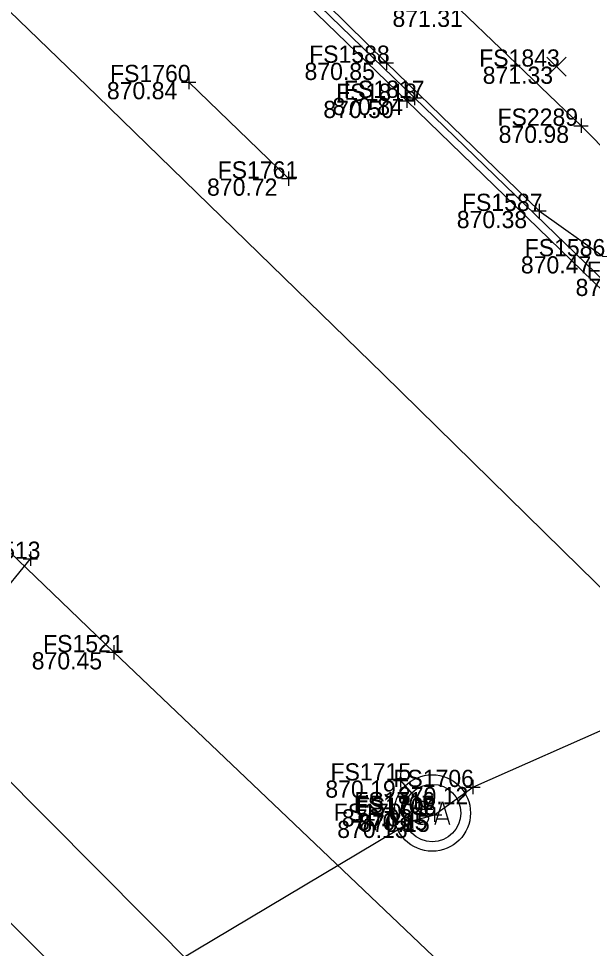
# Model space of a CAD drawing. Extents: x 1479420 to 1479833, y 379731 to 380103.
# Drawn here: x 1479593 to 1479633, y 379912.2 to 379977 of the extents above; entities that cross this region are included whole.
import ezdxf

# ---------------------------------------------------------------- set-up
doc = ezdxf.new("R2010")
doc.units = 0
for name, color, linetype in [('GK_Drainage_Nodes', 7, 'Continuous'), ('PM_X_CL_Double_Solid', 7, 'Continuous'), ('PM_X_Crosswalk', 7, 'Continuous'), ('PM_X_Lane_Line', 7, 'Continuous'), ('PV_X_Curb', 7, 'Continuous'), ('SV_X_Random_Point', 7, 'Continuous'), ('SV_X_Shot_Marker', 7, 'Continuous'), ('SV_X_Text_Elevation', 7, 'Continuous'), ('SV_X_Text_Name', 7, 'Continuous'), ('UT_X_Gas', 7, 'Continuous'), ('UT_X_Sanitary_Cells', 7, 'Continuous'), ('UT_X_Sanitary_Line', 7, 'Continuous'), ('UT_X_Water', 7, 'Continuous')]:
    doc.layers.add(name, color=color, linetype=linetype)

msp = doc.modelspace()

# ---------------------------------------------------------------- linework, layer by layer
at = {"layer": 'GK_Drainage_Nodes'}
for p, q in [((1479621.804, 379923.603), (1479621.804, 379923.603)), ((1479621.804, 379921.603), (1479621.804, 379921.603)), ((1479621.804, 379921.603), (1479621.804, 379921.603)), ((1479621.804, 379921.603), (1479621.804, 379921.603)), ((1479621.804, 379919.603), (1479621.804, 379919.603))]:
    msp.add_line(p, q, dxfattribs=at)
msp.add_circle((1479621.804, 379921.603), 2, dxfattribs=at)
at = {"layer": 'PM_X_CL_Double_Solid'}
msp.add_lwpolyline([(1479649.77, 379921.473), (1479632.094, 379938.759), (1479618.381, 379952.22), (1479598.438, 379971.627), (1479578.627, 379990.753), (1479560.467, 380008.345), (1479543.803, 380024.417)], dxfattribs=at)
at = {"layer": 'PM_X_Crosswalk'}
for p, q in [((1479636.371, 379879.555), (1479574.01, 379942.241)), ((1479627.792, 379878.685), (1479575.124, 379931.128))]:
    msp.add_line(p, q, dxfattribs=at)
at = {"layer": 'PM_X_Lane_Line'}
msp.add_line((1479604.82, 379972.583), (1479611.787, 379965.855), dxfattribs=at)
at = {"layer": 'PV_X_Curb'}
for points in [[(1479791.848, 380002.989), (1479773.254, 379993.873), (1479762.766, 379988.772), (1479738.122, 379976.643), (1479720.845, 379968.214), (1479698.694, 379957.239), (1479678.815, 379947.539), (1479674.951, 379945.56), (1479671.194, 379943.855), (1479668.836, 379942.929), (1479666.481, 379942.243), (1479664.295, 379941.704), (1479662.026, 379941.397), (1479659.994, 379941.512), (1479654.023, 379942.767), (1479648.758, 379945.101), (1479643.81, 379948.553), (1479642.638, 379949.516), (1479640.65, 379951.389), (1479638.379, 379953.495), (1479620.029, 379971.274), (1479601.931, 379988.801), (1479602.178, 379989.373), (1479582.142, 380008.015)], [(1479791.59, 380003.464), (1479772.982, 379994.381), (1479762.438, 379989.23), (1479737.891, 379977.225), (1479720.638, 379968.611), (1479698.71, 379957.883), (1479678.409, 379947.915), (1479674.816, 379946.157), (1479670.835, 379944.353), (1479668.74, 379943.532), (1479666.343, 379942.649), (1479664.179, 379942.195), (1479661.876, 379941.9), (1479659.999, 379941.971), (1479653.935, 379943.268), (1479649.182, 379945.527), (1479644.261, 379948.889), (1479643.432, 379949.993), (1479639.011, 379953.958), (1479638.818, 379953.848), (1479620.557, 379971.482), (1479582.44, 380008.391)]]:
    msp.add_lwpolyline(points, dxfattribs=at)
at = {"layer": 'SV_X_Random_Point'}
for p, q in [((1479629.807, 379972.993), (1479631.141, 379974.328)), ((1479629.807, 379974.328), (1479631.141, 379972.993))]:
    msp.add_line(p, q, dxfattribs=at)
at = {"layer": 'SV_X_Shot_Marker'}
for p, q in [((1479618.613, 379974.426), (1479618.613, 379973.426)), ((1479618.113, 379973.926), (1479619.113, 379973.926)), ((1479618.613, 379973.926), (1479618.613, 379973.926)), ((1479604.82, 379973.083), (1479604.82, 379972.083)), ((1479604.32, 379972.583), (1479605.32, 379972.583)), ((1479604.82, 379972.583), (1479604.82, 379972.583)), ((1479620.029, 379971.774), (1479620.029, 379970.774)), ((1479620.557, 379971.982), (1479620.557, 379970.982)), ((1479619.529, 379971.274), (1479620.529, 379971.274)), ((1479620.029, 379971.274), (1479620.029, 379971.274)), ((1479620.057, 379971.482), (1479621.057, 379971.482)), ((1479620.557, 379971.482), (1479620.557, 379971.482)), ((1479632.184, 379970.038), (1479632.184, 379969.038)), ((1479631.684, 379969.538), (1479632.684, 379969.538)), ((1479632.184, 379969.538), (1479632.184, 379969.538)), ((1479611.287, 379965.855), (1479612.287, 379965.855)), ((1479611.787, 379966.355), (1479611.787, 379965.355)), ((1479611.787, 379965.855), (1479611.787, 379965.855)), ((1479629.263, 379964.094), (1479629.263, 379963.094)), ((1479628.763, 379963.594), (1479629.763, 379963.594)), ((1479629.263, 379963.594), (1479629.263, 379963.594)), ((1479593.275, 379939.334), (1479594.275, 379939.334)), ((1479593.775, 379939.834), (1479593.775, 379938.834)), ((1479593.775, 379939.334), (1479593.775, 379939.334)), ((1479599.097, 379932.819), (1479600.097, 379932.819)), ((1479599.597, 379933.319), (1479599.597, 379932.319)), ((1479599.597, 379932.819), (1479599.597, 379932.819)), ((1479619.603, 379924.374), (1479619.603, 379923.374)), ((1479619.103, 379923.874), (1479620.103, 379923.874)), ((1479619.603, 379923.874), (1479619.603, 379923.874)), ((1479624.647, 379923.917), (1479624.647, 379922.917)), ((1479624.147, 379923.417), (1479625.147, 379923.417)), ((1479624.647, 379923.417), (1479624.647, 379923.417)), ((1479621.341, 379922.366), (1479621.341, 379921.366)), ((1479620.841, 379921.866), (1479621.841, 379921.866)), ((1479621.341, 379921.866), (1479621.341, 379921.866)), ((1479621.963, 379921.985), (1479621.963, 379920.985)), ((1479620.421, 379921.563), (1479620.421, 379920.563)), ((1479621.463, 379921.485), (1479622.463, 379921.485)), ((1479621.963, 379921.485), (1479621.963, 379921.485)), ((1479619.921, 379921.063), (1479620.921, 379921.063)), ((1479620.421, 379921.063), (1479620.421, 379921.063))]:
    msp.add_line(p, q, dxfattribs=at)
at = {"layer": 'UT_X_Gas'}
msp.add_lwpolyline([(1479590.076, 380006.869), (1479598.835, 379999.983), (1479606.591, 379993.985), (1479615.604, 379985.249), (1479623.747, 379977.629), (1479632.184, 379969.538), (1479638.836, 379962.809), (1479646.785, 379955.438), (1479652.981, 379949.433), (1479657.465, 379945.964), (1479660.591, 379945.024), (1479670.935, 379949.08), (1479679.157, 379953.065), (1479685.442, 379955.742), (1479689.462, 379958.127), (1479696.956, 379963.013), (1479705.088, 379967.488), (1479713.465, 379971.226), (1479723.024, 379975.676), (1479732.065, 379980.116), (1479742.535, 379985.018)], dxfattribs=at)
at = {"layer": 'UT_X_Sanitary_Cells'}
for points in [[(1479621.471, 379922.29), (1479621.446, 379922.315), (1479621.408, 379922.34), (1479621.295, 379922.378), (1479621.156, 379922.403), (1479621.056, 379922.403), (1479621.018, 379922.403), (1479620.854, 379922.365), (1479620.716, 379922.29), (1479620.627, 379922.189), (1479620.602, 379922.088), (1479620.602, 379922.013), (1479620.627, 379921.912), (1479620.728, 379921.824), (1479621.421, 379921.446), (1479621.484, 379921.396), (1479621.509, 379921.345), (1479621.534, 379921.27), (1479621.534, 379921.194), (1479621.522, 379921.118), (1479621.509, 379921.068), (1479621.484, 379921.005), (1479621.459, 379920.954), (1479621.434, 379920.917), (1479621.396, 379920.879), (1479621.358, 379920.854), (1479621.308, 379920.829), (1479621.27, 379920.816), (1479621.156, 379920.803), (1479620.98, 379920.803), (1479620.867, 379920.829), (1479620.703, 379920.917), (1479620.602, 379920.992)], [(1479622.013, 379920.803), (1479622.517, 379922.403), (1479623.008, 379920.803)], [(1479622.882, 379921.181), (1479622.139, 379921.181)]]:
    msp.add_lwpolyline(points, dxfattribs=at)
for radius in [2.667, 2]:
    msp.add_circle((1479621.804, 379921.603), radius, dxfattribs=at)
at = {"layer": 'UT_X_Sanitary_Line'}
msp.add_line((1479619.603, 379923.874), (1479621.341, 379921.866), dxfattribs=at)
msp.add_lwpolyline([(1479514.622, 379866.87), (1479542.109, 379880.195), (1479565.169, 379891.725), (1479588.442, 379902.577), (1479600.276, 379909.045), (1479620.421, 379921.063), (1479621.963, 379921.485), (1479624.647, 379923.417), (1479645.234, 379932.512), (1479652.585, 379935.616), (1479664.157, 379939.675), (1479679.103, 379944.837), (1479710.112, 379956.448), (1479736.037, 379968.233), (1479798.147, 379991.168), (1479820.4, 379999.933), (1479823.042, 380000.22)], dxfattribs=at)
at = {"layer": 'UT_X_Water'}
for points in [[(1479473.217, 380054.881), (1479498.741, 380029.974), (1479514.505, 380014.086), (1479533.448, 379996.735), (1479556.003, 379974.319), (1479574.861, 379956.271), (1479584.403, 379947.432), (1479599.597, 379932.819), (1479630.106, 379903.783), (1479644.769, 379889.722), (1479654.209, 379882.356), (1479664.266, 379872.629), (1479692.509, 379845.847), (1479712.672, 379826.686), (1479730.739, 379809.85), (1479753.15, 379788.309), (1479771.842, 379770.542), (1479781.678, 379761.101)], [(1479586.915, 380004.501), (1479604.754, 379987.567), (1479618.613, 379973.926), (1479629.263, 379963.594), (1479633.713, 379960.434), (1479641.035, 379960.303), (1479643.418, 379958.357), (1479650.478, 379950.403), (1479653.168, 379946.48), (1479654.757, 379940.471), (1479659.938, 379935.366), (1479675.346, 379920.322), (1479682.752, 379913.809), (1479688.353, 379908.314)], [(1479451.52, 379837.183), (1479469.615, 379848.275), (1479481.983, 379856.402), (1479496.242, 379865.929), (1479520, 379881.305), (1479538.557, 379892.999), (1479553.442, 379903.409), (1479554.944, 379904.326), (1479564.844, 379911.311), (1479573.24, 379917.005), (1479582.403, 379926.468), (1479585.515, 379929.786), (1479589.646, 379934.736), (1479591.405, 379936.451), (1479593.775, 379939.334)]]:
    msp.add_lwpolyline(points, dxfattribs=at)

# ---------------------------------------------------------------- texts
at = {"layer": 'SV_X_Text_Elevation'}
for s, p in [('871.31', (1479619.032, 379976.429)), ('870.85', (1479612.897, 379972.726)), ('871.33', (1479625.325, 379972.46)), ('870.84', (1479599.113, 379971.383)), ('870.50', (1479614.209, 379970.074)), ('870.84', (1479614.85, 379970.282)), ('870.98', (1479626.439, 379968.338)), ('870.72', (1479606.099, 379964.655)), ('870.38', (1479623.518, 379962.394)), ('870.47', (1479627.988, 379959.234)), ('870.65', (1479631.801, 379957.662)), ('870.45', (1479593.872, 379931.619)), ('870.19', (1479614.35, 379922.674)), ('870.12', (1479619.413, 379922.217)), ('870.08', (1479615.502, 379920.666)), ('870.13', (1479615.178, 379919.863)), ('870.15', (1479616.561, 379920.403)), ('870.15', (1479616.72, 379920.285))]:
    msp.add_text(s, height=1.2, dxfattribs=at).set_placement(p)
at = {"layer": 'SV_X_Text_Name'}
for s, p in [('FS1588', (1479613.219, 379973.926)), ('FS1843', (1479625.08, 379973.66)), ('FS1760', (1479599.331, 379972.583)), ('FS1818', (1479615.108, 379971.274)), ('FS1817', (1479615.645, 379971.482)), ('FS2289', (1479626.355, 379969.538)), ('FS1761', (1479606.836, 379965.855)), ('FS1587', (1479623.878, 379963.594)), ('FS1586', (1479628.253, 379960.434)), ('FS1971', (1479632.585, 379958.862)), ('FS1513', (1479588.863, 379939.334)), ('FS1521', (1479594.665, 379932.819)), ('FS1715', (1479614.71, 379923.874)), ('FS1706', (1479619.092, 379923.417)), ('FS1716', (1479616.373, 379921.866)), ('FS1707', (1479616.325, 379921.603)), ('FS1708', (1479616.474, 379921.485)), ('FS1709', (1479614.932, 379921.063))]:
    msp.add_text(s, height=1.2, dxfattribs=at).set_placement(p)

doc.saveas('drawing.dxf')
